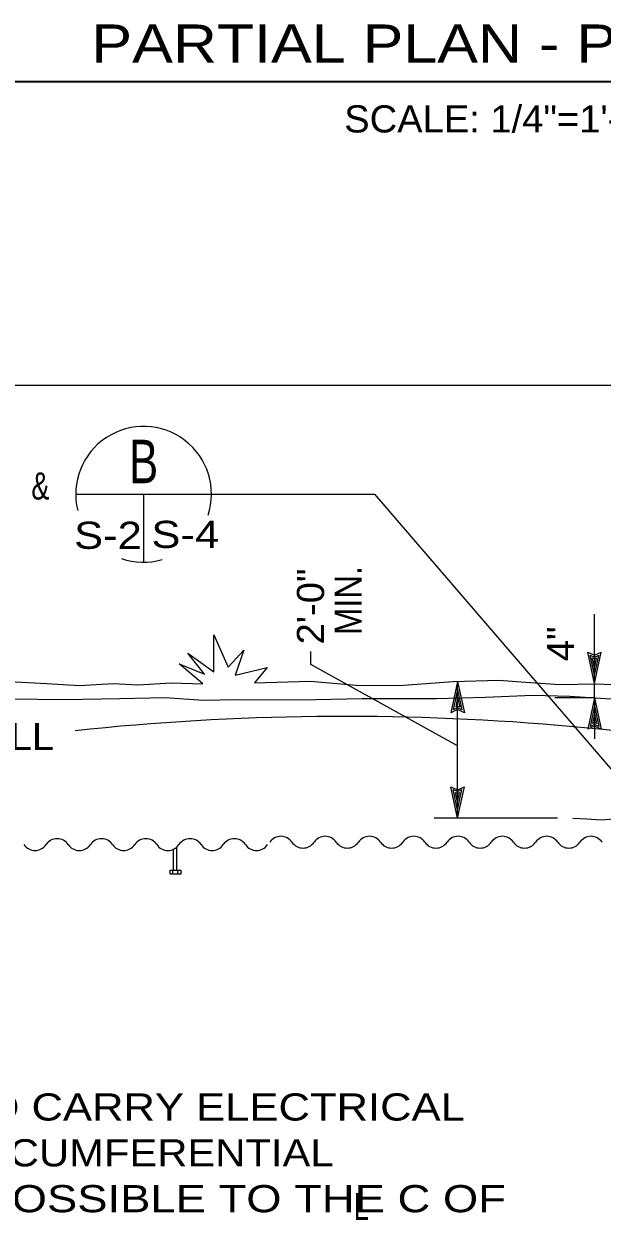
# Model space of a CAD drawing. Extents: x -22.3 to 19.7, y -11.8 to 18.2.
# Drawn here: x -7.13 to -4.47, y -5.67 to -0.16 of the extents above; entities that cross this region are included whole.
import ezdxf
from ezdxf.enums import TextEntityAlignment as Align

# ---------------------------------------------------------------- set-up
doc = ezdxf.new("R2010")
doc.units = 0
doc.header["$LTSCALE"] = 0.05
doc.layers.add('1', color=7, linetype='Continuous', lineweight=13)
doc.layers.add('2', color=7, linetype='Continuous', lineweight=13)

msp = doc.modelspace()

# ---------------------------------------------------------------- linework, layer by layer
at = {"layer": '1', "lineweight": 35}
msp.add_line((-7.37642, -0.42569), (-2.28642, -0.42569), dxfattribs=at)
at = {"layer": '1'}
for p, q in [((-8.41542, -1.82369), (-3.99142, -1.82369)), ((-4.50242, -3.19669), (-4.53342, -3.05269)), ((-4.50242, -3.15969), (-4.52242, -3.06569)), ((-4.52242, -3.06569), (-4.50242, -3.07469)), ((-4.50242, -3.12369), (-4.51242, -3.07869)), ((-4.51242, -3.07869), (-4.50242, -3.08269)), ((-4.50242, -3.19669), (-4.47142, -3.05269)), ((-4.50242, -3.15969), (-4.48242, -3.06569)), ((-4.50242, -3.07469), (-4.48242, -3.06569)), ((-4.50242, -3.12369), (-4.49342, -3.07869)), ((-4.50242, -3.08269), (-4.49342, -3.07869)), ((-5.13242, -3.18669), (-5.16342, -3.33069)), ((-5.13242, -3.81569), (-5.13242, -3.18669)), ((-5.13242, -3.18669), (-5.10142, -3.33069)), ((-5.13242, -3.22369), (-5.15242, -3.31769)), ((-5.13242, -3.22369), (-5.11242, -3.31769)), ((-5.13242, -3.25969), (-5.14142, -3.30469)), ((-5.13242, -3.30069), (-5.14142, -3.30469)), ((-5.13242, -3.25969), (-5.12242, -3.30469)), ((-5.12242, -3.30469), (-5.13242, -3.30069)), ((-4.50242, -3.26269), (-4.68442, -3.26269)), ((-4.50242, -3.26269), (-4.53342, -3.40669)), ((-4.50242, -3.29969), (-4.52242, -3.39369)), ((-4.50242, -3.26269), (-4.50242, -3.45069)), ((-4.50242, -3.26269), (-4.47142, -3.40669)), ((-4.50242, -3.29969), (-4.48242, -3.39369)), ((-5.13242, -3.30869), (-5.15242, -3.31769)), ((-5.11242, -3.31769), (-5.13242, -3.30869)), ((-4.50242, -3.33569), (-4.51142, -3.38069)), ((-4.50242, -3.33569), (-4.49242, -3.38069)), ((-4.50242, -3.38469), (-4.52242, -3.39369)), ((-4.50242, -3.37669), (-4.51142, -3.38069)), ((-4.49242, -3.38069), (-4.50242, -3.37669)), ((-4.48242, -3.39369), (-4.50242, -3.38469)), ((-5.13242, -3.81569), (-5.16342, -3.67169)), ((-5.13242, -3.77869), (-5.15242, -3.68469)), ((-5.15242, -3.68469), (-5.13242, -3.69369)), ((-5.13242, -3.81569), (-5.10142, -3.67169)), ((-5.13242, -3.77869), (-5.11242, -3.68469)), ((-5.13242, -3.69369), (-5.11242, -3.68469)), ((-5.13242, -3.74269), (-5.14242, -3.69769)), ((-5.14242, -3.69769), (-5.13242, -3.70169)), ((-5.13242, -3.74269), (-5.12342, -3.69769)), ((-5.13242, -3.70169), (-5.12342, -3.69769)), ((-4.67342, -3.81569), (-5.24042, -3.81569))]:
    msp.add_line(p, q, dxfattribs=at)
at = {"layer": '1', "lineweight": 25}
for p, q in [((-6.44042, -4.05469), (-6.44042, -3.95869)), ((-6.42542, -4.05469), (-6.42542, -3.95069)), ((-6.42542, -4.05469), (-6.42542, -3.95869)), ((-6.45642, -4.05469), (-6.40542, -4.05469)), ((-6.45642, -4.07169), (-6.45642, -4.05469)), ((-6.45642, -4.07169), (-6.40542, -4.07169)), ((-6.44342, -4.07169), (-6.44342, -4.05469)), ((-6.42042, -4.07169), (-6.42042, -4.05469)), ((-6.40542, -4.07169), (-6.40542, -4.05469))]:
    msp.add_line(p, q, dxfattribs=at)
for points in [[(-6.26642, -2.32569), (-5.51542, -2.32569), (-4.28642, -3.75369)], [(-7.19742, -3.18669), (-7.02342, -3.19569), (-6.87342, -3.20569), (-6.71842, -3.19669), (-6.60542, -3.20269), (-6.44942, -3.19369), (-6.30542, -3.19769), (-6.41442, -3.10569), (-6.29842, -3.15369), (-6.37442, -3.05669), (-6.25442, -3.14269), (-6.25542, -2.97269), (-6.18842, -3.12069), (-6.11642, -3.04269), (-6.15742, -3.15769), (-6.00942, -3.12269), (-6.06742, -3.19369), (-5.81142, -3.18569), (-5.58142, -3.20569), (-5.38242, -3.20469), (-5.15342, -3.18669), (-4.94342, -3.18169), (-4.81942, -3.18969), (-4.66242, -3.20069), (-4.49642, -3.19769), (-4.30442, -3.20569)], [(-7.18642, -3.26769), (-6.94542, -3.26969), (-6.68842, -3.26469), (-6.47842, -3.26069), (-6.30242, -3.27369), (-6.14842, -3.27069), (-5.85542, -3.27169), (-5.57142, -3.26469), (-5.41742, -3.26569), (-5.22942, -3.26569), (-5.00642, -3.25869), (-4.78642, -3.24969), (-4.61642, -3.25469), (-4.45142, -3.26569), (-4.30442, -3.27269), (-4.12542, -3.27069), (-3.99542, -3.26469), (-3.84342, -3.28769), (-3.73842, -3.28069), (-3.61442, -3.28869), (-3.50942, -3.28469), (-3.41242, -3.29069), (-3.31442, -3.28569)], [(-4.60242, -3.81569), (-4.53842, -3.81869), (-4.47242, -3.82369), (-4.41542, -3.81869)]]:
    msp.add_lwpolyline(points, dxfattribs=at)
at = {"layer": '1'}
for points in [[(-4.50242, -3.26269), (-4.50242, -3.19669), (-4.50242, -2.87669)], [(-5.13242, -3.48269), (-5.80842, -3.10969), (-5.80842, -3.04969)], [(-4.53342, -3.05269), (-4.50242, -3.06669), (-4.47142, -3.05269)], [(-5.10142, -3.33069), (-5.13242, -3.31669), (-5.16342, -3.33069)], [(-4.47142, -3.40669), (-4.50242, -3.39269), (-4.53342, -3.40669)], [(-5.16342, -3.67169), (-5.13242, -3.68569), (-5.10142, -3.67169)]]:
    msp.add_lwpolyline(points, dxfattribs=at)
msp.add_arc((-5.65272, -15.07871), 11.73082, 74.31555, 96.07119, dxfattribs=at)
at = {"layer": '1', "lineweight": 25}
for centre, start, end in [((-5.94642, -3.96119), 34.0772, 145.92281), ((-5.74242, -3.96119), 34.0772, 145.92281), ((-5.53842, -3.96119), 34.0772, 145.92281), ((-5.33442, -3.96119), 34.0772, 145.92281), ((-5.13042, -3.96119), 34.0772, 145.92281), ((-4.92642, -3.96119), 34.0772, 145.92281), ((-4.72242, -3.96119), 34.0772, 145.92281), ((-4.51842, -3.96119), 34.0772, 145.92281), ((-7.07842, -3.90319), 214.0772, 325.92281), ((-6.97642, -3.97219), 34.0772, 145.92281), ((-6.87442, -3.90319), 214.0772, 325.92281), ((-6.77242, -3.97219), 34.0772, 145.92281), ((-6.67042, -3.90319), 214.0772, 325.92281), ((-6.56842, -3.97219), 34.0772, 145.92281), ((-6.46642, -3.90319), 214.0772, 325.92281), ((-6.36442, -3.97219), 34.0772, 145.92281), ((-6.26242, -3.90319), 214.0772, 325.92281), ((-6.16042, -3.97219), 34.0772, 145.92281), ((-6.05842, -3.90319), 214.0772, 325.92281), ((-5.84442, -3.89219), 214.0772, 325.92281), ((-5.64042, -3.89219), 214.0772, 325.92281), ((-5.43642, -3.89219), 214.0772, 325.92281), ((-5.23242, -3.89219), 214.0772, 325.92281), ((-5.02842, -3.89219), 214.0772, 325.92281), ((-4.82442, -3.89219), 214.0772, 325.92281), ((-4.62042, -3.89219), 214.0772, 325.92281)]:
    msp.add_arc(centre, 0.06157, start, end, dxfattribs=at)
at = {"layer": '2', "lineweight": 25}
for p, q in [((-6.89042, -2.32569), (-6.26642, -2.32569)), ((-6.57842, -2.32569), (-6.57842, -2.63769))]:
    msp.add_line(p, q, dxfattribs=at)
for start, end in [(341.96976, 193.81208), (251.04049, 285.74671)]:
    msp.add_arc((-6.57842, -2.32569), 0.3125, start, end, dxfattribs=at)

# ---------------------------------------------------------------- texts
at = {"layer": '1'}
for s, height, width, p in [('PARTIAL PLAN - PORTAL WALL', 0.175, 1.2, (-4.71942, -0.33869)), ('SCALE: 1/4"=1\'-0"', 0.125, 1.05, (-4.93892, -0.66069)), ('&', 0.125, 0.75, (-7.05342, -2.34969)), ('IMPERVIOUS FILL', 0.125, 1.1, (-7.77742, -3.50269))]:
    msp.add_text(s, height=height, dxfattribs=dict(at, width=width)).set_placement(p, align=Align.CENTER)
at = {"layer": '1', "width": 1.05}
for s, p in [('2\'-0"', (-5.74742, -3.01669)), ('4"', (-4.59642, -3.09369))]:
    msp.add_text(s, height=0.125, rotation=90, dxfattribs=at).set_placement(p)
at = {"layer": '1', "width": 0.9}
msp.add_text('MIN.', height=0.125, rotation=90, dxfattribs=at).set_placement((-5.57442, -2.81419), align=Align.CENTER)
at = {"layer": '1'}
for s, width, p in [('WITH DOUBLE NUT TO CARRY ELECTRICAL', 1.2, (-9.34542, -5.20769)), ('CONDUIT AT EACH CIRCUMFERENTIAL', 1.15, (-9.34542, -5.41869)), ('SEAM, AS NEAR AS POSSIBLE TO THE C OF', 1.25, (-9.34542, -5.62969)), ('L', 0.75, (-5.61142, -5.66569))]:
    msp.add_text(s, height=0.125, dxfattribs=dict(at, width=width)).set_placement(p)
at = {"layer": '2'}
for s, height, width, p in [('B', 0.2, 0.75, (-6.57792, -2.27469)), ('S-2', 0.125, 1.2, (-6.74242, -2.57669)), ('S-4', 0.125, 1.2, (-6.38642, -2.57269))]:
    msp.add_text(s, height=height, dxfattribs=dict(at, width=width)).set_placement(p, align=Align.CENTER)

doc.saveas('drawing.dxf')
